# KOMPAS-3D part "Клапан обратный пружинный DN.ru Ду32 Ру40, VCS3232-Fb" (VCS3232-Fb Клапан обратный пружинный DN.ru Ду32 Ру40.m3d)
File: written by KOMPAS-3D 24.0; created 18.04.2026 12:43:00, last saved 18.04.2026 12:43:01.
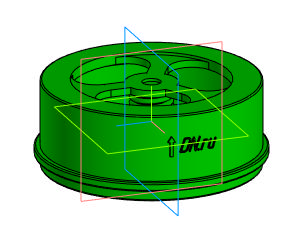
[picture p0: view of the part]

Document properties: Автор: 712; Полное имя файла: C:\Users\712\Desktop\Новая папка (4)\VCS3232-Fb Клапан обратный пружинный DN.ru Ду32 Ру40.m3d

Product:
- Component: Пружина 1086-0796 ГОСТ 18793-80  | qty 1  | additional columns: 3953604318-4147491677-0; Деталь; Пользователь Windows; c; Шероховатость не задана; Да; Сталь 10  ГОСТ 1050-88; source file: Деталь_1.m3d
- Body: Тело 1  | qty 1
    Масса: 0.345088
- Part/product: Клапан обратный пружинный DN.ru Ду32 Ру40  | designation VCS3232-Fb
    Масса: 0.47
    Раздел спецификации: Прочие изделия
    Примечание: D100-03889
    additional columns: 071bd168-1a06-425c-849c-e99e84a96128; Деталь; 712; c; Шероховатость не задана; Да

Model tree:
1. Операция без истории:2

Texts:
  VCS3232-Fb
